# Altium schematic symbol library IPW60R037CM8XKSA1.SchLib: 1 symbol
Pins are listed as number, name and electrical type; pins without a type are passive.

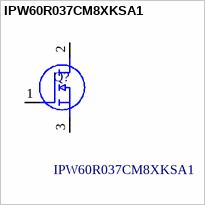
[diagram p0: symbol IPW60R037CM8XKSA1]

## IPW60R037CM8XKSA1
designator Q?
Suitableforhardandsoftswitchingtopologiesthankstoan outstandingcommutationruggedness Significantreductionofswitchingandconductionlosses BestinclassRDS(on)perpackageproductsenabledbyultralowRDS(on)*A; Manufacturer_Name: Infineon; Geometry.Height: 5.21mm
footprint TO544P521X1592X2557-3P
pins: 1 G, 2 D, 3 S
